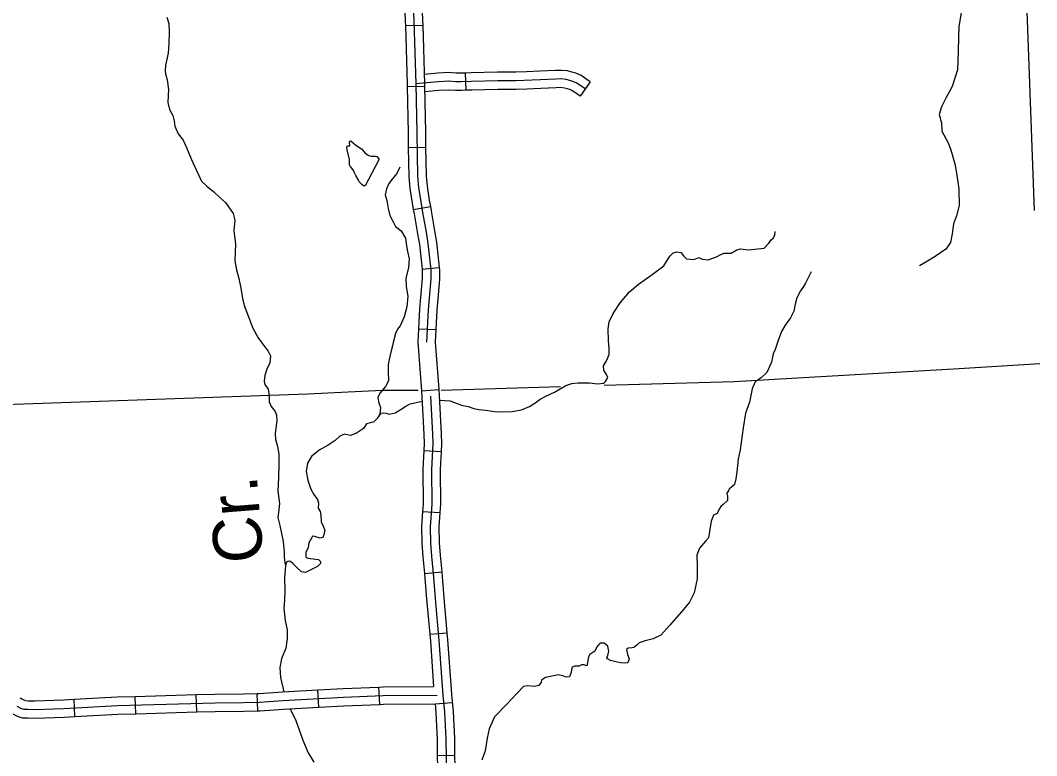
# Model space of a CAD drawing. Extents: x -5566 to 1759129, y -3726 to 731467.
# Drawn here: x -4560.5 to -4493.8, y 298.6 to 346.9 of the extents above; entities that cross this region are included whole.
import ezdxf

# ---------------------------------------------------------------- set-up
doc = ezdxf.new("R2010")
doc.units = 0
doc.layers.add('Default', color=7, linetype='Continuous')

msp = doc.modelspace()

# ---------------------------------------------------------------- linework, layer by layer
at = {"layer": 'Default'}
for p, q in [((-4535.238, 346.567), (-4534.1, 346.599)), ((-4531.31, 343.452), (-4531.262, 342.314)), ((-4535.127, 342.564), (-4533.988, 342.586)), ((-4523.105, 342.873), (-4523.76, 341.941)), ((-4535.053, 338.557), (-4533.914, 338.575)), ((-4534.723, 334.477), (-4533.602, 334.679)), ((-4534.148, 330.552), (-4533.016, 330.673)), ((-4534.376, 326.641), (-4533.238, 326.583)), ((-4534.186, 322.57), (-4533.05, 322.654)), ((-4534.039, 318.633), (-4532.901, 318.582)), ((-4534.115, 314.64), (-4532.979, 314.561)), ((-4533.985, 310.544), (-4532.852, 310.657)), ((-4533.643, 306.555), (-4532.508, 306.656)), ((-4548.95, 301.453), (-4548.983, 302.592)), ((-4544.944, 301.534), (-4544.972, 302.672)), ((-4540.925, 301.761), (-4540.984, 302.899)), ((-4536.924, 301.951), (-4536.975, 303.089)), ((-4556.949, 301.148), (-4557.011, 302.286)), ((-4552.958, 301.337), (-4552.991, 302.476)), ((-4533.294, 301.987), (-4532.158, 302.069)), ((-4533.145, 298.594), (-4532.006, 298.614))]:
    msp.add_line(p, q, dxfattribs=at)
for points in [[(-4535.164, 358.87), (-4534.677, 346.865), (-4534.561, 342.732)], [(-4534.259, 350.613), (-4534.108, 346.884), (-4534.1, 346.599)], [(-4535.397, 350.567), (-4535.246, 346.845), (-4535.238, 346.567)], [(-4494.434, 348.102), (-4493.922, 334.407)], [(-4498.711, 347.529), (-4498.878, 346.509), (-4498.891, 345.823), (-4498.925, 344.854), (-4498.972, 343.655), (-4499.327, 342.56), (-4499.732, 341.791), (-4500.015, 341.232), (-4500.164, 340.731), (-4500.022, 340.18), (-4499.987, 339.64), (-4499.604, 338.915), (-4499.396, 338.404), (-4499.116, 337.4), (-4499, 336.711), (-4498.885, 335.831), (-4498.86, 334.734), (-4499.041, 334.065), (-4499.226, 333.54), (-4499.316, 332.881), (-4499.432, 332.305), (-4499.743, 331.875), (-4500.424, 331.393), (-4500.937, 331.093), (-4501.464, 330.769)], [(-4550.918, 347.131), (-4550.789, 346.716), (-4550.761, 346.146), (-4550.793, 345.36), (-4550.832, 344.749), (-4550.935, 344.257), (-4551, 343.957), (-4551.017, 343.591), (-4551.002, 343.393), (-4550.89, 343.009), (-4550.814, 342.379), (-4550.837, 341.966), (-4550.858, 341.508), (-4550.735, 341.063), (-4550.523, 340.659), (-4550.427, 340.312), (-4550.392, 339.963), (-4550.168, 339.445), (-4549.842, 339.038), (-4549.62, 338.565), (-4549.319, 337.807), (-4548.957, 337.035), (-4548.636, 336.345), (-4548.29, 336.022), (-4547.82, 335.635), (-4547.444, 335.298), (-4547.051, 334.931), (-4546.554, 334.217), (-4546.447, 333.772), (-4546.506, 333.099), (-4546.404, 332.196), (-4546.417, 331.7), (-4546.456, 331.096), (-4546.343, 330.506), (-4546.186, 329.947), (-4546.049, 329.312), (-4545.948, 328.622), (-4545.833, 328.169), (-4545.498, 327.312), (-4545.262, 326.673), (-4544.906, 326.053), (-4544.49, 325.474), (-4544.259, 325.177), (-4544.103, 324.855), (-4544.155, 324.411), (-4544.337, 323.978), (-4544.481, 323.569), (-4544.521, 323.201), (-4544.475, 322.975), (-4544.266, 322.67), (-4544.182, 322.231), (-4544.183, 321.834), (-4544.066, 321.534), (-4543.803, 321.2), (-4543.718, 320.959), (-4543.682, 320.602), (-4543.803, 319.752), (-4543.774, 319.364), (-4543.643, 318.896), (-4543.557, 318.397), (-4543.564, 317.756), (-4543.569, 316.857), (-4543.628, 315.97), (-4543.507, 315.159), (-4543.584, 314.562), (-4543.618, 314.233), (-4543.5, 313.719), (-4543.272, 312.668), (-4543.216, 311.946), (-4543.211, 311.618), (-4543.154, 311.285)], [(-4534.1, 346.599), (-4533.991, 342.745), (-4533.988, 342.586)], [(-4535.238, 346.567), (-4535.13, 342.718), (-4535.127, 342.564)], [(-4531.31, 343.452), (-4531.592, 343.441), (-4531.917, 343.434), (-4532.384, 343.478), (-4533.116, 343.432), (-4534.009, 343.358)], [(-4527.293, 343.538), (-4527.993, 343.518), (-4529.184, 343.508), (-4530.923, 343.468), (-4531.31, 343.452)], [(-4523.105, 342.873), (-4523.685, 343.28), (-4524.035, 343.44), (-4524.299, 343.515), (-4524.584, 343.587), (-4524.976, 343.628), (-4525.371, 343.626), (-4526.383, 343.564), (-4527.293, 343.538)], [(-4535.127, 342.564), (-4535.068, 339.517), (-4535.053, 338.557)], [(-4523.433, 342.407), (-4523.97, 342.784), (-4524.232, 342.904), (-4524.447, 342.965), (-4524.684, 343.025), (-4525.004, 343.059), (-4525.352, 343.057), (-4526.358, 342.995), (-4527.983, 342.949), (-4529.175, 342.939), (-4530.905, 342.899), (-4531.574, 342.871), (-4531.937, 342.863), (-4532.393, 342.906), (-4533.075, 342.863), (-4533.826, 342.802), (-4534.561, 342.732)], [(-4534.561, 342.732), (-4534.499, 339.527), (-4534.454, 336.663), (-4534.377, 335.935), (-4534.237, 334.991), (-4534.111, 334.289), (-4533.885, 332.986), (-4533.758, 332.25), (-4533.572, 330.516), (-4533.58, 329.927), (-4533.672, 328.657), (-4533.754, 327.896), (-4533.784, 327.057), (-4533.85, 325.76)], [(-4533.988, 342.586), (-4533.929, 339.537), (-4533.914, 338.575)], [(-4531.262, 342.314), (-4531.556, 342.302), (-4531.958, 342.293), (-4532.402, 342.335), (-4533.034, 342.295), (-4533.981, 342.217)], [(-4527.261, 342.399), (-4527.972, 342.379), (-4529.167, 342.369), (-4530.886, 342.33), (-4531.262, 342.314)], [(-4523.76, 341.941), (-4524.254, 342.287), (-4524.429, 342.368), (-4524.594, 342.414), (-4524.785, 342.463), (-4525.033, 342.489), (-4525.333, 342.488), (-4526.332, 342.426), (-4527.261, 342.399)], [(-4538.654, 337.035), (-4538.75, 337.201), (-4538.88, 337.322), (-4538.924, 337.427), (-4538.924, 337.531), (-4538.906, 337.653), (-4538.924, 337.766), (-4539.071, 338.409), (-4539.089, 338.574), (-4539.071, 338.652), (-4539.002, 338.661), (-4538.898, 338.661), (-4538.898, 338.721), (-4538.915, 338.808), (-4538.915, 338.904), (-4538.898, 338.974), (-4538.872, 339), (-4538.802, 338.982), (-4538.507, 338.713), (-4538.133, 338.461), (-4537.994, 338.313), (-4537.89, 338.174)], [(-4535.053, 338.557), (-4535.023, 336.628), (-4534.942, 335.864), (-4534.799, 334.899), (-4534.723, 334.477)], [(-4533.914, 338.575), (-4533.885, 336.698), (-4533.811, 336.007), (-4533.675, 335.083), (-4533.602, 334.679)], [(-4537.89, 338.174), (-4537.638, 338.026), (-4537.482, 337.991), (-4537.334, 337.991), (-4537.212, 337.991), (-4537.117, 337.974), (-4536.986, 337.809), (-4536.986, 337.748), (-4537.89, 336.027), (-4537.985, 336.027), (-4538.107, 336.123), (-4538.281, 336.297), (-4538.342, 336.453), (-4538.507, 336.723), (-4538.611, 336.94), (-4538.654, 337.035)], [(-4536.986, 337.748), (-4537.89, 336.027)], [(-4535.612, 337.267), (-4535.666, 337.103), (-4535.824, 336.83), (-4536.099, 336.47), (-4536.324, 336.187), (-4536.486, 335.838), (-4536.563, 335.447), (-4536.461, 335.079)], [(-4536.461, 335.079), (-4536.373, 334.539), (-4536.263, 334.091), (-4536.05, 333.68), (-4535.881, 333.373), (-4535.514, 333.089), (-4535.23, 332.596), (-4535.166, 332.103), (-4535.092, 331.725), (-4534.983, 331.241), (-4535.045, 330.644), (-4535.203, 329.975), (-4535.198, 329.427), (-4535.091, 328.791), (-4535.156, 328.072), (-4535.33, 327.433), (-4535.59, 326.844), (-4535.749, 326.618), (-4535.89, 326.323), (-4536.04, 325.74), (-4536.081, 325.516), (-4536.173, 325.181), (-4536.262, 324.815), (-4536.362, 324.286), (-4536.365, 323.804), (-4536.348, 323.222)], [(-4533.602, 334.679), (-4533.55, 334.388), (-4533.324, 333.083), (-4533.193, 332.329), (-4533.016, 330.673)], [(-4534.723, 334.477), (-4534.672, 334.19), (-4534.446, 332.888), (-4534.322, 332.171), (-4534.148, 330.552)], [(-4533.003, 321.942), (-4532.307, 321.903), (-4531.554, 321.629), (-4531.121, 321.537), (-4530.753, 321.404), (-4530.409, 321.34), (-4529.975, 321.295), (-4529.372, 321.21), (-4528.885, 321.182), (-4528.225, 321.206), (-4527.607, 321.312), (-4527.09, 321.521), (-4526.734, 321.74), (-4526.387, 322.019), (-4525.978, 322.24), (-4525.455, 322.464), (-4525.061, 322.692), (-4524.689, 322.904), (-4524.299, 323.047), (-4523.891, 323.092), (-4523.427, 323.086), (-4523.139, 323.097), (-4522.613, 323.017), (-4522.212, 323.061), (-4522.102, 323.165), (-4521.937, 323.445), (-4522.028, 323.64), (-4522.198, 323.923), (-4522.223, 324.197), (-4522.038, 324.539), (-4521.863, 324.957), (-4521.854, 325.338), (-4521.896, 325.847), (-4521.925, 326.646), (-4521.842, 327.091), (-4521.582, 327.65), (-4521.129, 328.344), (-4520.51, 329.068), (-4519.921, 329.569), (-4519.122, 330.139), (-4518.264, 330.78), (-4517.862, 331.412), (-4517.642, 331.633), (-4517.402, 331.687), (-4517.149, 331.643), (-4516.96, 331.444), (-4516.778, 331.237), (-4516.29, 331.186), (-4515.954, 331.328), (-4515.745, 331.221), (-4515.356, 331.182), (-4514.794, 331.378), (-4514.481, 331.549), (-4514.286, 331.602), (-4513.831, 331.618), (-4513.466, 331.822), (-4513.218, 331.884), (-4512.693, 331.834), (-4511.664, 331.948), (-4511.372, 332.271), (-4511.227, 332.459), (-4511.088, 332.594), (-4510.974, 332.803), (-4510.944, 333.026)], [(-4534.148, 330.552), (-4534.142, 330.49), (-4534.149, 329.951), (-4534.24, 328.709), (-4534.323, 327.937), (-4534.353, 327.082), (-4534.376, 326.641)], [(-4533.016, 330.673), (-4533.002, 330.543), (-4533.01, 329.902), (-4533.105, 328.606), (-4533.186, 327.856), (-4533.215, 327.032), (-4533.238, 326.583)], [(-4508.586, 330.382), (-4508.961, 329.645), (-4509.09, 329.426), (-4509.284, 329.137), (-4509.518, 328.679), (-4509.624, 328.256), (-4509.722, 327.796), (-4509.933, 327.353), (-4510.28, 326.876), (-4510.538, 326.463), (-4510.759, 325.86), (-4510.943, 325.274), (-4511.085, 324.987), (-4511.178, 324.435), (-4511.488, 323.761), (-4511.87, 323.419), (-4512.263, 323.161), (-4512.451, 322.682), (-4512.631, 321.807), (-4512.886, 321.089), (-4513.049, 320.13), (-4513.239, 318.683), (-4513.369, 318.076), (-4513.46, 317.242), (-4513.534, 316.767), (-4513.612, 316.413), (-4513.965, 316.096), (-4514, 316.034), (-4514.115, 315.839), (-4514.084, 315.627), (-4514.074, 315.36), (-4514.353, 315.099), (-4514.507, 314.948), (-4514.615, 314.777), (-4514.765, 314.504), (-4514.996, 314.389), (-4515.141, 313.996), (-4515.328, 312.891), (-4515.526, 312.678), (-4515.927, 312.229), (-4516.085, 311.766), (-4516.065, 311.028), (-4516.081, 310.197), (-4516.268, 309.29), (-4516.564, 308.678), (-4516.972, 308.19), (-4517.868, 307.16), (-4518.451, 306.498), (-4518.951, 306.259), (-4519.478, 306.126), (-4519.883, 305.989), (-4520.044, 305.846), (-4520.221, 305.68), (-4520.341, 305.66), (-4520.606, 305.643), (-4520.71, 305.556), (-4520.652, 305.23), (-4520.535, 304.945), (-4520.624, 304.675), (-4520.829, 304.652), (-4521.103, 304.673), (-4521.501, 304.78), (-4521.769, 304.831), (-4521.97, 304.946), (-4522.011, 305.021), (-4521.948, 305.16), (-4521.867, 305.445), (-4521.948, 305.785), (-4522.182, 305.967), (-4522.433, 305.974), (-4522.536, 305.878), (-4522.66, 305.737), (-4522.786, 305.45), (-4523.112, 305.233), (-4523.22, 305.084), (-4523.275, 304.701), (-4523.328, 304.493), (-4523.512, 304.54), (-4523.664, 304.55), (-4523.82, 304.468), (-4524.124, 304.457), (-4524.303, 304.382), (-4524.345, 304.06), (-4524.448, 303.767), (-4524.674, 303.736), (-4524.891, 303.835), (-4525.181, 303.893), (-4526.033, 303.725), (-4526.292, 303.533), (-4526.318, 303.41), (-4526.469, 303.191), (-4526.763, 303.127), (-4527.205, 303.18), (-4527.491, 303.116), (-4527.923, 302.674), (-4528.572, 301.956), (-4529.393, 301.127), (-4529.736, 300.352), (-4529.865, 299.722), (-4530.002, 298.887), (-4530.216, 298.292)], [(-4534.376, 326.641), (-4534.421, 325.754), (-4534.186, 322.57)], [(-4533.238, 326.583), (-4533.28, 325.767), (-4533.05, 322.654)], [(-4493.546, 324.34), (-4498.852, 324.014), (-4513.631, 323.155), (-4522.17, 322.906)], [(-4536.348, 323.222), (-4536.545, 322.849), (-4536.924, 322.416), (-4537.057, 322.122), (-4536.976, 321.782), (-4536.881, 321.465), (-4536.927, 321.059), (-4537.054, 320.796), (-4537.31, 320.527), (-4537.543, 320.458), (-4537.791, 320.396), (-4538.001, 320.091), (-4538.46, 319.769), (-4538.849, 319.633), (-4539.231, 319.704), (-4539.538, 319.571), (-4539.854, 319.3), (-4540.322, 318.993), (-4540.902, 318.668), (-4541.418, 318.238), (-4541.668, 317.809), (-4541.769, 317.265), (-4541.657, 316.689), (-4541.453, 316.087), (-4541.258, 315.736), (-4541.019, 315.424), (-4540.942, 315.183), (-4540.961, 314.855), (-4540.831, 314.638), (-4540.807, 314.395), (-4540.768, 313.94), (-4540.644, 313.662), (-4540.528, 313.407), (-4540.64, 312.938), (-4540.835, 312.87), (-4541.196, 312.979), (-4541.334, 313.012), (-4541.42, 312.887), (-4541.576, 312.569), (-4541.633, 312.27), (-4541.773, 311.929), (-4541.793, 311.852), (-4541.777, 311.632), (-4541.66, 311.552), (-4540.944, 311.471), (-4540.817, 311.339), (-4540.828, 311.201), (-4541.025, 311.004), (-4541.801, 310.625), (-4542.076, 310.668), (-4542.375, 310.955), (-4542.611, 311.198), (-4542.784, 311.352), (-4542.921, 311.362), (-4543.055, 311.296), (-4543.116, 311.088)], [(-4534.396, 322.573), (-4536.761, 322.575), (-4541.679, 322.332), (-4565.335, 321.499)], [(-4534.186, 322.57), (-4534.156, 322.174), (-4534.022, 319.698), (-4534.018, 319.105), (-4534.039, 318.633)], [(-4533.05, 322.654), (-4533.02, 322.247), (-4532.883, 319.733), (-4532.878, 319.083), (-4532.901, 318.582)], [(-4525.056, 322.822), (-4532.889, 322.593)], [(-4537.054, 320.796), (-4536.822, 321.094), (-4536.702, 321.121), (-4536.503, 321.09), (-4536.304, 321.036), (-4535.912, 321.104), (-4535.585, 321.312), (-4535.214, 321.554), (-4534.928, 321.708), (-4534.14, 321.872)], [(-4533.588, 322.21), (-4533.452, 319.715), (-4533.448, 319.094), (-4533.525, 317.394), (-4533.512, 315.103), (-4533.614, 313.624), (-4533.583, 312.543), (-4533.528, 311.702), (-4533.389, 310.302), (-4533.282, 308.917), (-4533.035, 306.147), (-4532.777, 302.561), (-4532.669, 301.437), (-4532.594, 299.684), (-4532.55, 297.117), (-4532.473, 295.185), (-4532.386, 291.842), (-4531.989, 282.511)], [(-4534.039, 318.633), (-4534.095, 317.406), (-4534.082, 315.121), (-4534.115, 314.64)], [(-4532.901, 318.582), (-4532.955, 317.383), (-4532.943, 315.085), (-4532.979, 314.561)], [(-4534.115, 314.64), (-4534.184, 313.635), (-4534.152, 312.516), (-4534.096, 311.655), (-4533.985, 310.544)], [(-4532.979, 314.561), (-4533.044, 313.612), (-4533.014, 312.569), (-4532.961, 311.748), (-4532.852, 310.657)], [(-4543.154, 311.285), (-4543.116, 311.088), (-4543.177, 310.263), (-4543.169, 309.41), (-4543.186, 308.83), (-4543.218, 308.249), (-4543.144, 307.475), (-4543.015, 306.847), (-4543.017, 306.29), (-4543.1, 305.639), (-4543.371, 304.944), (-4543.487, 304.383), (-4543.44, 303.714), (-4543.224, 302.784)], [(-4533.985, 310.544), (-4533.956, 310.252), (-4533.849, 308.87), (-4533.643, 306.555)], [(-4532.852, 310.657), (-4532.821, 310.353), (-4532.714, 308.964), (-4532.508, 306.656)], [(-4533.643, 306.555), (-4533.602, 306.101), (-4533.389, 303.126)], [(-4532.508, 306.656), (-4532.467, 306.193), (-4532.212, 302.648)], [(-4552.991, 302.476), (-4548.983, 302.592)], [(-4548.983, 302.592), (-4547.761, 302.628), (-4545.88, 302.65), (-4544.972, 302.672)], [(-4544.972, 302.672), (-4544.853, 302.675), (-4543.316, 302.778), (-4540.984, 302.899)], [(-4543.283, 302.209), (-4539.306, 302.415), (-4536.697, 302.531), (-4533.157, 302.558)], [(-4540.984, 302.899), (-4539.333, 302.984), (-4536.975, 303.089)], [(-4536.975, 303.089), (-4536.712, 303.101), (-4533.389, 303.126)], [(-4532.212, 302.648), (-4532.209, 302.609), (-4532.1, 301.476), (-4532.025, 299.701), (-4532.006, 298.614)], [(-4560.762, 301.833), (-4560.526, 301.712), (-4560.304, 301.638), (-4560.042, 301.625), (-4559.577, 301.611), (-4557.68, 301.679), (-4554.155, 301.872), (-4547.75, 302.058), (-4545.87, 302.081), (-4544.827, 302.106), (-4543.283, 302.209)], [(-4560.541, 302.39), (-4560.446, 302.312), (-4560.304, 302.239), (-4560.197, 302.203), (-4560.019, 302.194), (-4559.579, 302.181), (-4557.706, 302.248), (-4557.011, 302.286)], [(-4557.011, 302.286), (-4554.179, 302.441), (-4552.991, 302.476)], [(-4540.925, 301.761), (-4539.278, 301.846), (-4536.924, 301.951)], [(-4536.924, 301.951), (-4536.682, 301.962), (-4533.294, 301.987)], [(-4533.294, 301.987), (-4533.237, 301.397), (-4533.163, 299.667), (-4533.145, 298.594)], [(-4561.266, 301.511), (-4561.077, 301.355), (-4560.748, 301.186), (-4560.411, 301.073), (-4560.064, 301.056), (-4559.575, 301.041), (-4557.654, 301.11), (-4556.949, 301.148)], [(-4556.949, 301.148), (-4554.131, 301.303), (-4552.958, 301.337)], [(-4552.958, 301.337), (-4548.95, 301.453)], [(-4548.95, 301.453), (-4547.738, 301.489), (-4545.859, 301.511), (-4544.944, 301.534)], [(-4544.944, 301.534), (-4544.801, 301.537), (-4543.249, 301.641), (-4540.925, 301.761)], [(-4542.802, 301.664), (-4542.449, 300.884), (-4541.984, 299.598), (-4541.635, 298.757), (-4541.264, 298.145)], [(-4533.145, 298.594), (-4533.12, 297.101), (-4533.043, 295.166), (-4533.027, 294.581)], [(-4532.006, 298.614), (-4531.981, 297.133), (-4531.904, 295.203), (-4531.889, 294.611)]]:
    msp.add_lwpolyline(points, dxfattribs=at)

# ---------------------------------------------------------------- texts
msp.add_text('Cr.', height=3.2048, rotation=94.55013, dxfattribs=at).set_placement((-4544.556, 311.366))

doc.saveas('drawing.dxf')
